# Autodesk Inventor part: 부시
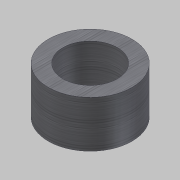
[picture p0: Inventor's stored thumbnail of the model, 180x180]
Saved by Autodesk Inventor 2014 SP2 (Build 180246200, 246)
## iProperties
Company: 한국ATC센터
Created: 2014-10
Part Number: 부시
Document SubType Name: Modeling
Designer: 한국ATC센터
Density: 7.86 g/cm^3
Material: 강, 연강
Mass: 157.788 g
Surface Area: 70.2617 cm^2
Volume: 20.0748 cm^3
Appearance: 금속-강(기계 가공_02)
Author: KYOUNG IL JANG
Revision Number: 1
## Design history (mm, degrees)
sketch "스케치1"
  geometry: C1 r 21.5 at (0, 0) reference; C2 r 31 at (0, 0) reference; C3 r 14 at (0, 0) reference; 1 further point
  node "참조1"
  node "참조2"
node "작업 평면1"
extrude "돌출1" new body sketch "스케치1" stored distance "d0" = 10; taper "d1" = 0 deg
node "솔리드1"
